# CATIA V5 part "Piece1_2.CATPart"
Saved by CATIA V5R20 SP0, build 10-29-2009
Part number: Pièce1
Bounding box of the stored display mesh (mm): x 0 to 5, y -17.976 to 32.024, z -43.726 to 6.274
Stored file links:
  C:\Users\ASUS\Desktop\Think Motion IAO\Piece1_2.CATPart
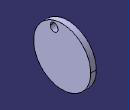
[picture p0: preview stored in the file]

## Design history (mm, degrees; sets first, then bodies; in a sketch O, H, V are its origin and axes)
Body1 (main body)
  Plane1: stored without definition
  Point1 "Point.O": stored without definition
  Point2 "Point.A": stored without definition
  Sketch1 on Plane1, origin (0, 0, 0), H (0, 1, 0), V (0, 0, 1)
    circle A1 centre (7.024, -18.726) radius 25
    reference projected point E1 (7.024, -18.726) from Point1
    circle A2 centre (0, 0) radius 3.5
    reference projected point E2 (0, 0) from Point2
    radius A1 = 25
    radius A2 = 3.5
    concentricity: E1 A1, A2 E2
  Pad1: profile Sketch1, direction (1, 0, 0), length 5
